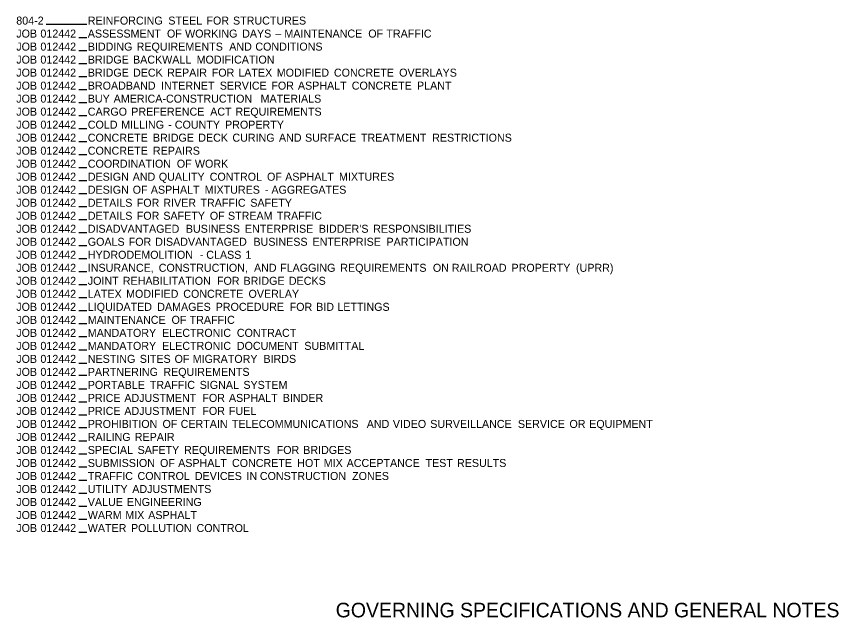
# Model space of a CAD drawing. Extents: x 1930579 to 1932219, y 596452 to 599493.
# Drawn here: x 1931525 to 1932204, y 598495 to 598990 of the extents above; entities that cross this region are included whole.
import ezdxf

# ---------------------------------------------------------------- set-up
doc = ezdxf.new("R2010")
doc.units = 0
doc.layers.add('Default', color=7, linetype='Continuous')
doc.layers.add('R_Border', color=7, linetype='Continuous')

msp = doc.modelspace()

# ---------------------------------------------------------------- linework, layer by layer
at = {"layer": 'R_Border'}
for p, q in [((1931549.9, 598983.67), (1931583.53, 598983.67)), ((1931576.86, 598972.89), (1931583.53, 598972.89)), ((1931576.86, 598962.16), (1931583.53, 598962.16)), ((1931576.86, 598951.44), (1931583.53, 598951.44)), ((1931576.86, 598940.71), (1931583.53, 598940.71)), ((1931576.86, 598929.99), (1931583.53, 598929.99)), ((1931576.86, 598919.26), (1931583.53, 598919.26)), ((1931576.86, 598908.54), (1931583.53, 598908.54)), ((1931576.86, 598897.81), (1931583.53, 598897.81)), ((1931576.86, 598887.09), (1931583.53, 598887.09)), ((1931576.86, 598876.36), (1931583.53, 598876.36)), ((1931576.86, 598865.64), (1931583.53, 598865.64)), ((1931576.86, 598854.91), (1931583.53, 598854.91)), ((1931576.86, 598844.19), (1931583.53, 598844.19)), ((1931576.86, 598833.46), (1931583.53, 598833.46)), ((1931576.86, 598822.74), (1931583.53, 598822.74)), ((1931576.86, 598812.01), (1931583.53, 598812.01)), ((1931576.86, 598801.29), (1931583.53, 598801.29)), ((1931576.86, 598790.56), (1931583.53, 598790.56)), ((1931576.86, 598779.84), (1931583.53, 598779.84)), ((1931576.86, 598769.11), (1931583.53, 598769.11)), ((1931576.86, 598758.39), (1931583.53, 598758.39)), ((1931576.86, 598747.66), (1931583.53, 598747.66)), ((1931576.86, 598736.94), (1931583.53, 598736.94)), ((1931576.86, 598726.23), (1931583.53, 598726.23)), ((1931576.86, 598715.35), (1931583.53, 598715.35)), ((1931576.86, 598704.47), (1931583.53, 598704.47)), ((1931576.86, 598694.32), (1931583.53, 598694.32)), ((1931576.86, 598683.25), (1931583.53, 598683.25)), ((1931576.86, 598672.55), (1931583.53, 598672.55)), ((1931576.86, 598661.74), (1931583.53, 598661.74)), ((1931576.86, 598651.26), (1931583.53, 598651.26)), ((1931576.86, 598640.26), (1931583.53, 598640.26)), ((1931576.86, 598629.47), (1931583.53, 598629.47)), ((1931576.86, 598618.82), (1931583.53, 598618.82)), ((1931576.86, 598607.93), (1931583.53, 598607.93)), ((1931576.86, 598597.2), (1931583.53, 598597.2)), ((1931576.86, 598586.55), (1931583.53, 598586.55)), ((1931576.86, 598575.66), (1931583.53, 598575.66)), ((1931576.86, 598564.93), (1931583.53, 598564.93))]:
    msp.add_line(p, q, dxfattribs=at)

# ---------------------------------------------------------------- texts
at = {"layer": 'Default'}
for s, p in [('804-2', (1931525.34, 598983.42)), ('REINFORCING', (1931584.33, 598983.42)), (' STEEL', (1931648.3, 598983.42)), (' FOR', (1931679.76, 598983.42)), (' STRUCTURES', (1931701.66, 598983.42)), ('JOB', (1931525.34, 598972.7)), (' 012442', (1931542.79, 598972.7)), ('ASSESSMENT', (1931584.33, 598972.7)), (' OF', (1931647.18, 598972.7)), (' WORKING', (1931662.13, 598972.7)), (' DAYS', (1931709.19, 598972.7)), ('–', (1931738.95, 598972.7)), (' MAINTENANCE', (1931744.05, 598972.7)), (' OF', (1931813.25, 598972.7)), (' TRAFFIC', (1931828.19, 598972.7)), ('JOB', (1931525.34, 598961.97)), (' 012442', (1931542.79, 598961.97)), ('BIDDING', (1931584.33, 598961.97)), (' REQUIREMENTS', (1931622.18, 598961.97)), (' AND', (1931698.55, 598961.97)), (' CONDITIONS', (1931720.09, 598961.97)), ('JOB', (1931525.34, 598951.25)), (' 012442', (1931542.79, 598951.25)), ('BRIDGE', (1931584.33, 598951.25)), (' BACKWALL', (1931619.19, 598951.25)), (' MODIFICATION', (1931671.65, 598951.25)), ('JOB', (1931525.34, 598940.52)), (' 012442', (1931542.79, 598940.52)), ('BRIDGE', (1931584.33, 598940.52)), (' DECK', (1931619.19, 598940.52)), (' REPAIR', (1931647.36, 598940.52)), (' FOR', (1931684.13, 598940.52)), (' LATEX', (1931706.03, 598940.52)), (' MODIFIED', (1931737.75, 598940.52)), (' CONCRETE', (1931784.9, 598940.52)), (' OVERLAYS', (1931838.72, 598940.52)), ('JOB', (1931525.34, 598929.8)), (' 012442', (1931542.79, 598929.8)), ('BROADBAND', (1931584.33, 598929.8)), (' INTERNET', (1931642.26, 598929.8)), (' SERVICE', (1931690.75, 598929.8)), (' FOR', (1931733.3, 598929.8)), (' ASPHALT', (1931755.21, 598929.8)), (' CONCRETE', (1931799.61, 598929.8)), (' PLANT', (1931853.43, 598929.8)), ('JOB', (1931525.34, 598919.07)), (' 012442', (1931542.79, 598919.07)), ('BUY', (1931584.33, 598919.07)), (' AMERICA-CONSTRUCTION', (1931603.22, 598919.07)), (' MATERIALS', (1931724.41, 598919.07)), ('JOB', (1931525.34, 598908.35)), (' 012442', (1931542.79, 598908.35)), ('CARGO', (1931584.33, 598908.35)), (' PREFERENCE', (1931617.73, 598908.35)), (' ACT', (1931682.84, 598908.35)), (' REQUIREMENTS', (1931703.66, 598908.35)), ('JOB', (1931525.34, 598897.62)), (' 012442', (1931542.79, 598897.62)), ('COLD', (1931584.33, 598897.62)), (' MILLING', (1931609.45, 598897.62)), (' -', (1931648.32, 598897.62)), (' COUNTY', (1931653.67, 598897.62)), (' PROPERTY', (1931695.1, 598897.62)), ('JOB', (1931525.34, 598886.9)), (' 012442', (1931542.79, 598886.9)), ('CONCRETE', (1931584.33, 598886.9)), (' BRIDGE', (1931635.59, 598886.9)), (' DECK', (1931673.01, 598886.9)), (' CURING', (1931701.18, 598886.9)), (' AND', (1931739.54, 598886.9)), (' SURFACE', (1931761.08, 598886.9)), (' TREATMENT', (1931807.22, 598886.9)), (' RESTRICTIONS', (1931865.95, 598886.9)), ('JOB', (1931525.34, 598876.17)), (' 012442', (1931542.79, 598876.17)), ('CONCRETE', (1931584.33, 598876.17)), (' REPAIRS', (1931635.59, 598876.17)), ('JOB', (1931525.34, 598865.45)), (' 012442', (1931542.79, 598865.45)), ('COORDINATION', (1931584.33, 598865.45)), (' OF', (1931655.3, 598865.45)), (' WORK', (1931670.25, 598865.45)), ('JOB', (1931525.34, 598854.72)), (' 012442', (1931542.79, 598854.72)), ('DESIGN', (1931584.33, 598854.72)), (' AND', (1931618.93, 598854.72)), (' QUALITY', (1931640.47, 598854.72)), (' CONTROL', (1931682.42, 598854.72)), (' OF', (1931729.74, 598854.72)), (' ASPHALT', (1931744.69, 598854.72)), (' MIXTURES', (1931789.09, 598854.72)), ('JOB', (1931525.34, 598844)), (' 012442', (1931542.79, 598844)), ('DESIGN', (1931584.33, 598844)), (' OF', (1931618.93, 598844)), (' ASPHALT', (1931633.88, 598844)), (' MIXTURES', (1931678.28, 598844)), (' -', (1931728.01, 598844)), (' AGGREGATES', (1931733.36, 598844)), ('JOB', (1931525.34, 598833.27)), (' 012442', (1931542.79, 598833.27)), ('DETAILS', (1931584.33, 598833.27)), (' FOR', (1931622.28, 598833.27)), (' RIVER', (1931644.18, 598833.27)), (' TRAFFIC', (1931674.81, 598833.27)), (' SAFETY', (1931715.93, 598833.27)), ('JOB', (1931525.34, 598822.55)), (' 012442', (1931542.79, 598822.55)), ('DETAILS', (1931584.33, 598822.55)), (' FOR', (1931622.28, 598822.55)), (' SAFETY', (1931644.18, 598822.55)), (' OF', (1931682.55, 598822.55)), (' STREAM', (1931697.5, 598822.55)), (' TRAFFIC', (1931737.8, 598822.55)), ('JOB', (1931525.34, 598811.82)), (' 012442', (1931542.79, 598811.82)), ('DISADVANTAGED', (1931584.33, 598811.82)), (' BUSINESS', (1931662.76, 598811.82)), (' ENTERPRISE', (1931711.48, 598811.82)), (" BIDDER'S", (1931772.48, 598811.82)), (' RESPONSIBILITIES', (1931817.32, 598811.82)), ('JOB', (1931525.34, 598801.1)), (' 012442', (1931542.79, 598801.1)), ('GOALS', (1931584.33, 598801.1)), (' FOR', (1931615.62, 598801.1)), (' DISADVANTAGED', (1931637.52, 598801.1)), (' BUSINESS', (1931718.52, 598801.1)), (' ENTERPRISE', (1931767.24, 598801.1)), (' PARTICIPATION', (1931828.24, 598801.1)), ('JOB', (1931525.34, 598790.37)), (' 012442', (1931542.79, 598790.37)), ('HYDRODEMOLITION', (1931584.33, 598790.37)), (' CLASS', (1931679.6, 598790.37)), (' 1', (1931711.93, 598790.37)), (' -', (1931674.26, 598790.37)), ('JOB', (1931525.34, 598779.65)), (' 012442', (1931542.79, 598779.65)), ('INSURANCE,', (1931584.33, 598779.65)), (' CONSTRUCTION,', (1931640.39, 598779.65)), (' AND', (1931718.98, 598779.65)), (' FLAGGING', (1931740.52, 598779.65)), (' REQUIREMENTS', (1931790.15, 598779.65)), (' ON', (1931866.53, 598779.65)), (' RAILROAD', (1931882.17, 598779.65)), (' PROPERTY', (1931931.39, 598779.65)), (' (UPRR)', (1931984.61, 598779.65)), ('JOB', (1931525.34, 598768.92)), (' 012442', (1931542.79, 598768.92)), ('JOINT', (1931584.33, 598768.92)), (' REHABILITATION', (1931610.78, 598768.92)), (' FOR', (1931688.43, 598768.92)), (' BRIDGE', (1931710.33, 598768.92)), (' DECKS', (1931747.76, 598768.92)), ('JOB', (1931525.34, 598758.2)), (' 012442', (1931542.79, 598758.2)), ('LATEX', (1931584.33, 598758.2)), (' MODIFIED', (1931613.48, 598758.2)), (' CONCRETE', (1931660.63, 598758.2)), (' OVERLAY', (1931714.46, 598758.2)), ('JOB', (1931525.34, 598747.47)), (' 012442', (1931542.79, 598747.47)), ('LIQUIDATED', (1931584.33, 598747.47)), (' DAMAGES', (1931639.17, 598747.47)), (' PROCEDURE', (1931687.38, 598747.47)), (' FOR', (1931748.38, 598747.47)), (' BID', (1931770.28, 598747.47)), (' LETTINGS', (1931787.72, 598747.47)), ('JOB', (1931525.34, 598736.75)), (' 012442', (1931542.79, 598736.75)), ('MAINTENANCE', (1931584.33, 598736.75)), (' OF', (1931650.96, 598736.75)), (' TRAFFIC', (1931665.91, 598736.75)), ('JOB', (1931525.34, 598726.02)), (' 012442', (1931542.79, 598726.02)), ('MANDATORY', (1931584.33, 598726.02)), (' ELECTRONIC', (1931643.18, 598726.02)), (' CONTRACT', (1931704.82, 598726.02)), ('JOB', (1931525.34, 598715.3)), (' 012442', (1931542.79, 598715.3)), ('MANDATORY', (1931584.33, 598715.3)), (' ELECTRONIC', (1931643.18, 598715.3)), (' DOCUMENT', (1931704.82, 598715.3)), (' SUBMITTAL', (1931760.47, 598715.3)), ('JOB', (1931525.34, 598704.57)), (' 012442', (1931542.79, 598704.57)), ('NESTING', (1931584.33, 598704.57)), (' SITES', (1931624.74, 598704.57)), (' OF', (1931653.47, 598704.57)), (' MIGRATORY', (1931668.42, 598704.57)), (' BIRDS', (1931726.76, 598704.57)), ('JOB', (1931525.34, 598693.85)), (' 012442', (1931542.79, 598693.85)), ('PARTNERING', (1931584.33, 598693.85)), (' REQUIREMENTS', (1931644.21, 598693.85)), ('JOB', (1931525.34, 598683.12)), (' 012442', (1931542.79, 598683.12)), ('PORTABLE', (1931584.33, 598683.12)), (' TRAFFIC', (1931633.04, 598683.12)), (' SIGNAL', (1931674.17, 598683.12)), (' SYSTEM', (1931710.22, 598683.12)), ('JOB', (1931525.34, 598672.4)), (' 012442', (1931542.79, 598672.4)), ('PRICE', (1931584.33, 598672.4)), (' ADJUSTMENT', (1931612.02, 598672.4)), (' FOR', (1931676.39, 598672.4)), (' ASPHALT', (1931698.3, 598672.4)), (' BINDER', (1931742.7, 598672.4)), ('JOB', (1931525.34, 598661.67)), (' 012442', (1931542.79, 598661.67)), ('PRICE', (1931584.33, 598661.67)), (' ADJUSTMENT', (1931612.02, 598661.67)), (' FOR', (1931676.39, 598661.67)), (' FUEL', (1931698.3, 598661.67)), ('JOB', (1931525.34, 598650.95)), (' 012442', (1931542.79, 598650.95)), ('PROHIBITION', (1931584.33, 598650.95)), (' OF', (1931643.52, 598650.95)), (' CERTAIN', (1931658.47, 598650.95)), (' TELECOMMUNICATIONS', (1931700.75, 598650.95)), (' AND', (1931811.97, 598650.95)), (' VIDEO', (1931833.51, 598650.95)), (' SURVEILLANCE', (1931864.35, 598650.95)), (' SERVICE', (1931936.64, 598650.95)), (' OR', (1931979.19, 598650.95)), (' EQUIPMENT', (1931995.46, 598650.95)), ('JOB', (1931525.34, 598640.22)), (' 012442', (1931542.79, 598640.22)), ('RAILING', (1931584.33, 598640.22)), (' REPAIR', (1931620.64, 598640.22)), ('JOB', (1931525.34, 598629.5)), (' 012442', (1931542.79, 598629.5)), ('SPECIAL', (1931584.33, 598629.5)), (' SAFETY', (1931622.96, 598629.5)), (' REQUIREMENTS', (1931661.32, 598629.5)), (' FOR', (1931737.7, 598629.5)), (' BRIDGES', (1931759.6, 598629.5)), ('JOB', (1931525.34, 598618.77)), (' 012442', (1931542.79, 598618.77)), ('SUBMISSION', (1931584.33, 598618.77)), (' OF', (1931641.48, 598618.77)), (' ASPHALT', (1931656.42, 598618.77)), (' CONCRETE', (1931700.83, 598618.77)), (' HOT', (1931754.65, 598618.77)), (' MIX', (1931776.49, 598618.77)), (' ACCEPTANCE', (1931795.39, 598618.77)), (' TEST', (1931860.49, 598618.77)), (' RESULTS', (1931886.44, 598618.77)), ('JOB', (1931525.34, 598608.05)), (' 012442', (1931542.79, 598608.05)), ('TRAFFIC', (1931584.33, 598608.05)), (' CONTROL', (1931622.9, 598608.05)), (' DEVICES', (1931670.22, 598608.05)), (' IN', (1931712.79, 598608.05)), (' CONSTRUCTION', (1931723.81, 598608.05)), (' ZONES', (1931799.91, 598608.05)), ('JOB', (1931525.34, 598597.32)), (' 012442', (1931542.79, 598597.32)), ('UTILITY', (1931584.33, 598597.32)), (' ADJUSTMENTS', (1931618.58, 598597.32)), ('JOB', (1931525.34, 598586.6)), (' 012442', (1931542.79, 598586.6)), (' ENGINEERING', (1931614.08, 598586.6)), ('VALUE', (1931584.33, 598586.6)), ('JOB', (1931525.34, 598575.87)), (' 012442', (1931542.79, 598575.87)), ('WARM', (1931584.33, 598575.87)), (' MIX', (1931612.83, 598575.87)), (' ASPHALT', (1931631.72, 598575.87)), ('JOB', (1931525.34, 598565.15)), (' 012442', (1931542.79, 598565.15)), ('WATER', (1931584.33, 598565.15)), (' POLLUTION', (1931617.5, 598565.15)), (' CONTROL', (1931671.58, 598565.15))]:
    msp.add_text(s, height=6.6, dxfattribs=at).set_placement(p)
at = {"layer": 'R_Border'}
msp.add_text('GOVERNING SPECIFICATIONS AND GENERAL NOTES', height=12, rotation=360, dxfattribs=at).set_placement((1931788.84, 598494.83))

doc.saveas('drawing.dxf')
